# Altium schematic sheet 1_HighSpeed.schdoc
size 561 x 251 mm
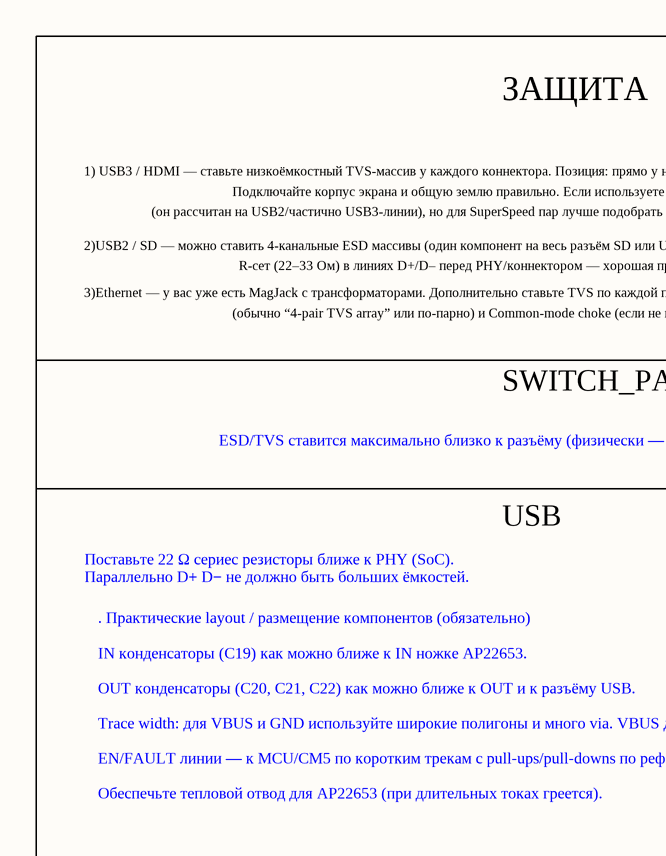
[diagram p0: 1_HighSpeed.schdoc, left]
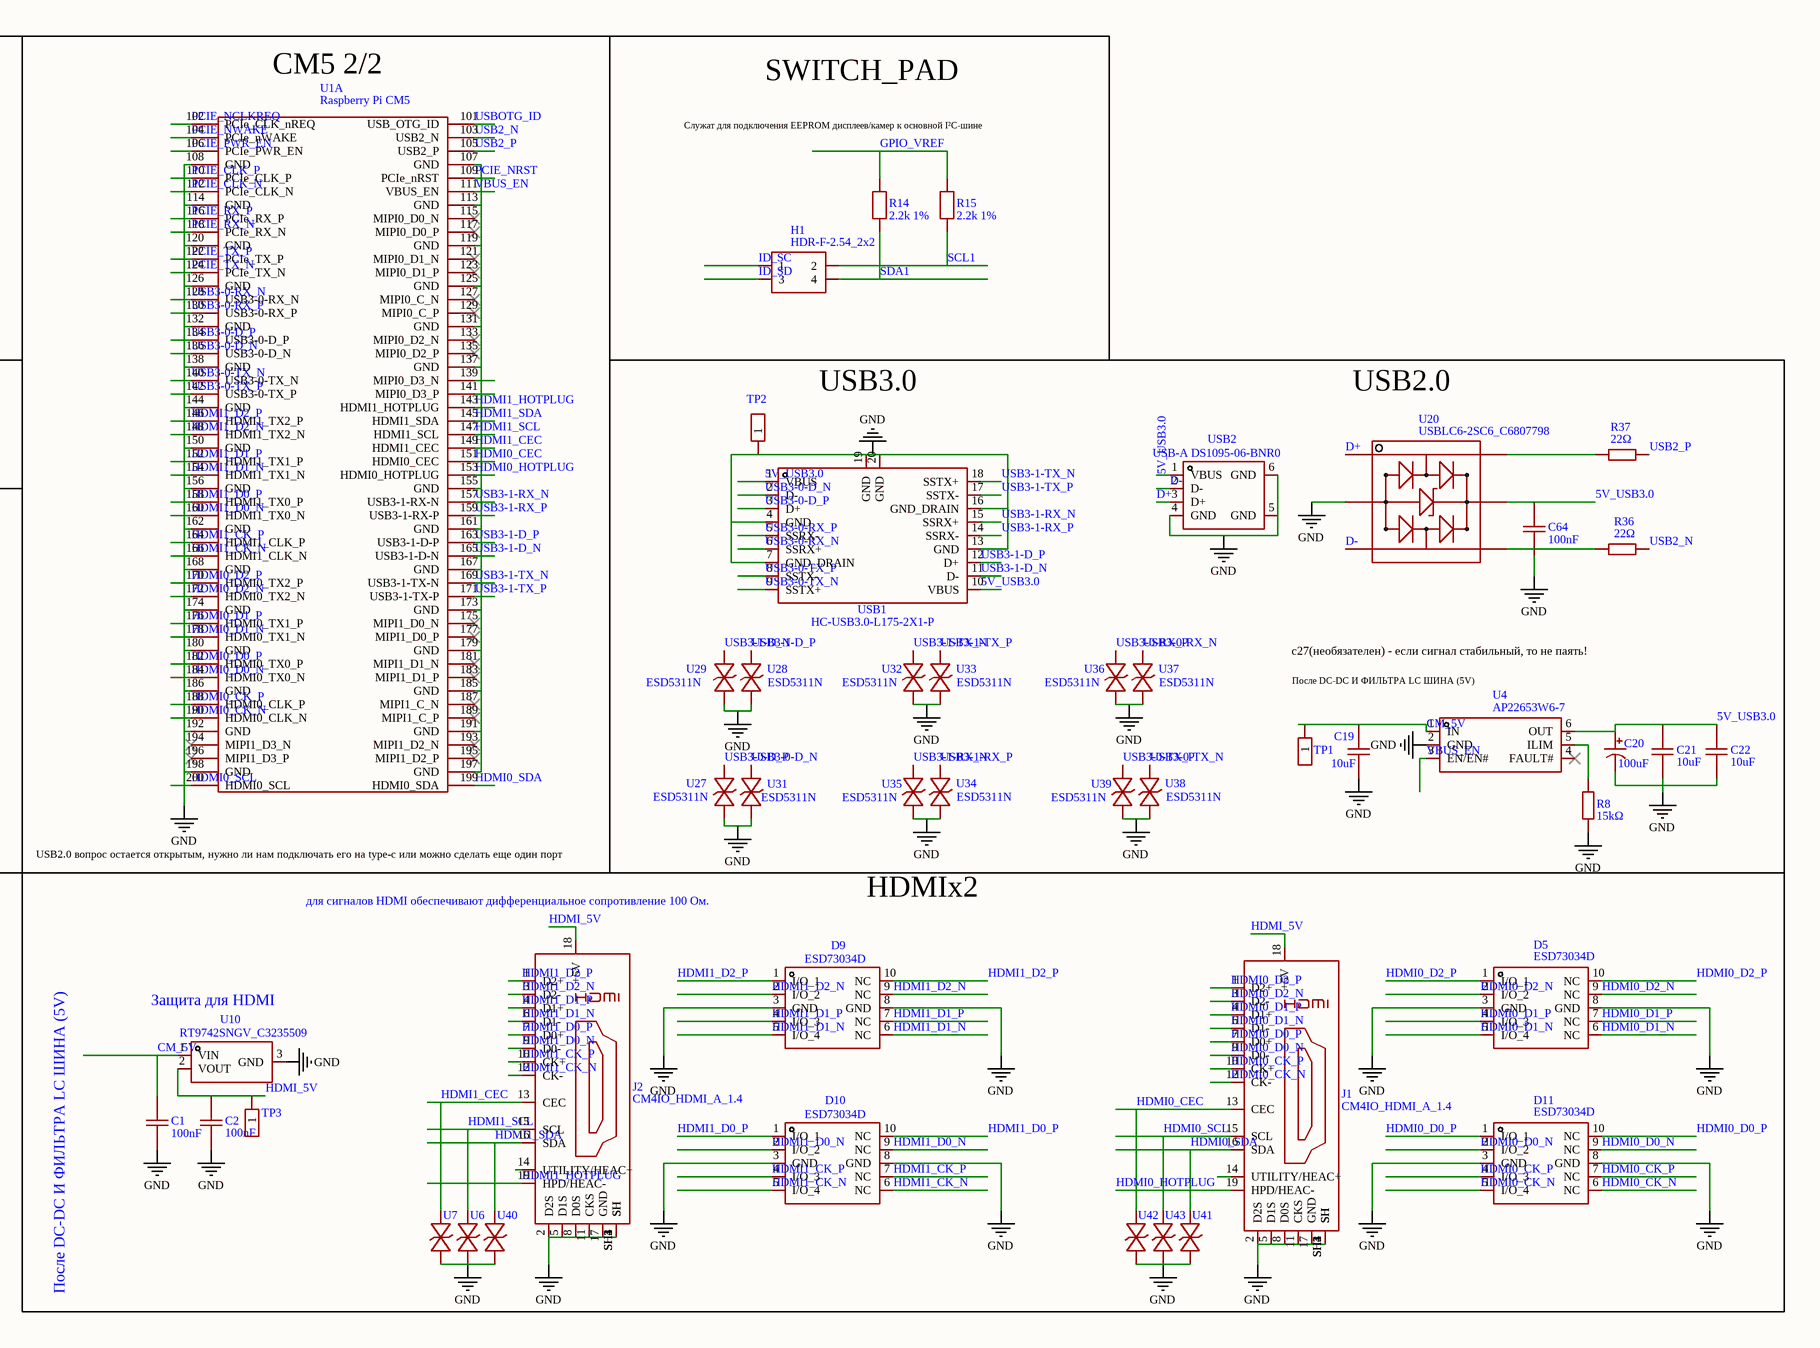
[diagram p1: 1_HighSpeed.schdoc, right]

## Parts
C1  100nF  [C0603]
C2  100nF  [C0603]
C19  10uF  [C0603]
C20  100uF  [CAP-SMD_BD6.3-L6.6-W6.6-LS7.6-FD]
C21  10uF  [C0603]
C22  10uF  [C0603]
C64  100nF  [C0402]
D5  ESD73034D  [DFN-10_L2.5-W1.0-P0.50-BL-2]
D9  ESD73034D  [DFN-10_L2.5-W1.0-P0.50-BL-2]
D10  ESD73034D  [DFN-10_L2.5-W1.0-P0.50-BL-2]
D11  ESD73034D  [DFN-10_L2.5-W1.0-P0.50-BL-2]
H1  HDR-F-2.54_2x2  [HDR-F-2.54_2X2]
J1  CM4IO_HDMI_A_1.4  [EDAC 690-019-298-412]
J2  CM4IO_HDMI_A_1.4  [EDAC 690-019-298-412]
R8  15kΩ  [R0603]
R14  2.2k 1%  [R0603]
R15  2.2k 1%  [R0603]
R36  22Ω  [R0402]
R37  22Ω  [R0402]
TP1  HDR-M-2.54_1x1  [HDR-M-2.54_1X1]  (value not drawn)
TP2  HDR-M-2.54_1x1  [HDR-M-2.54_1X1]  (value not drawn)
TP3  HDR-M-2.54_1x1  [HDR-M-2.54_1X1]  (value not drawn)
U1  Raspberry Pi CM5  [CM5IO:Raspberry-Pi-5-Compute-Module]  (part A of 2)
U4  AP22653W6-7  [SOT-23-6_L2.9-W1.6-P0.95-LS2.8-BR]
U6  ESD5311N  [DFN1006-2L-BI]  (value not drawn)
U7  ESD5311N  [DFN1006-2L-BI]  (value not drawn)
U10  RT9742SNGV_C3235509  [SOT-23-3_L2.9-W1.6-P1.90-LS2.8-BR]
U20  USBLC6-2SC6_C6807798  [SOT-23-6_L2.9-W1.6-P0.95-LS2.8-BL]
U27  ESD5311N  [DFN1006-2L-BI]
U28  ESD5311N  [DFN1006-2L-BI]
U29  ESD5311N  [DFN1006-2L-BI]
U31  ESD5311N  [DFN1006-2L-BI]
U32  ESD5311N  [DFN1006-2L-BI]
U33  ESD5311N  [DFN1006-2L-BI]
U34  ESD5311N  [DFN1006-2L-BI]
U35  ESD5311N  [DFN1006-2L-BI]
U36  ESD5311N  [DFN1006-2L-BI]
U37  ESD5311N  [DFN1006-2L-BI]
U38  ESD5311N  [DFN1006-2L-BI]
U39  ESD5311N  [DFN1006-2L-BI]
U40  ESD5311N  [DFN1006-2L-BI]  (value not drawn)
U41  ESD5311N  [DFN1006-2L-BI]  (value not drawn)
U42  ESD5311N  [DFN1006-2L-BI]  (value not drawn)
U43  ESD5311N  [DFN1006-2L-BI]  (value not drawn)
USB1  HC-USB3.0-L175-2X1-P  [USB-A-TH_H181-AF2R06-12ALCR]
USB2  USB-A DS1095-06-BNR0  [DS1095-06-BNR0]

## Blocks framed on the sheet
CM5 2/2: U1
SWITCH_PAD: H1 R14 R15
HDMIx2: C1 C2 D5 D9-D11 J1 J2 TP3 U6 U7 U10 U40-U43

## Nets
GND: C1.1 C2.1 C19.1 C20.2 C21.1 C22.1 C64.2 D5.3(GND) D5.8(GND) D9.3(GND) D9.8(GND) D10.3(GND) D10.8(GND) D11.3(GND) D11.8(GND) J1.2(D2S) J1.5(D1S) J1.8(D0S) J1.11(CKS) J1.17(GND) J1.SH1(SH) J1.SH2(SH) J1.SH3(SH) J1.SH4(SH) J2.2(D2S) J2.5(D1S) J2.8(D0S) J2.11(CKS) J2.17(GND) J2.SH1(SH) J2.SH2(SH) J2.SH3(SH) J2.SH4(SH) R8.1 TP2.1 U1.108(GND) U1.114(GND) U1.120(GND) U1.126(GND) U1.132(GND) U1.138(GND) U1.144(GND) U1.150(GND) U1.156(GND) U1.162(GND) U1.168(GND) U1.174(GND) U1.180(GND) U1.186(GND) U1.192(GND) U1.198(GND) U4.2(GND) U6.1 U7.1 U10.3(GND) U20.2(GND) U27.1 U28.1 U29.1 U31.1 U32.1 U33.1 U34.1 U35.1 U36.1 U37.1 U38.1 U39.1 U40.1 U41.1 U42.1 U43.1 USB1.4(GND) USB1.7(GND_DRAIN) USB1.13(GND) USB1.16(GND_DRAIN) USB1.19(GND) USB1.20(GND) USB2.4(GND) USB2.5(GND) USB2.6(GND)
5V_USB3.0: C20.1 C21.2 C22.2 C64.1 U4.6(OUT) U20.5(VCC) USB1.1(VBUS) USB1.10(VBUS) USB2.1(VBUS)
CM_5V: C1.2 C19.2 TP1.1 U4.1(IN) U10.1(VIN)
D+: U20.1(I/O1) USB2.3(D+)
D-: U20.3(I/O2) USB2.2(D-)
GPIO_VREF: R14.2 R15.2
HDMI0_CEC: J1.13(CEC) U1.151(HDMI0_CEC) U42.2
HDMI0_CK_N: D11.5(I/O_4) D11.6(NC) J1.12(CK-) U1.190(HDMI0_CLK_N)
HDMI0_CK_P: D11.4(I/O_3) D11.7(NC) J1.10(CK+) U1.188(HDMI0_CLK_P)
HDMI0_D0_N: D11.2(I/O_2) D11.9(NC) J1.9(D0-) U1.184(HDMI0_TX0_N)
HDMI0_D0_P: D11.1(I/O_1) D11.10(NC) J1.7(D0+) U1.182(HDMI0_TX0_P)
HDMI0_D1_N: D5.5(I/O_4) D5.6(NC) J1.6(D1-) U1.178(HDMI0_TX1_N)
HDMI0_D1_P: D5.4(I/O_3) D5.7(NC) J1.4(D1+) U1.176(HDMI0_TX1_P)
HDMI0_D2_N: D5.2(I/O_2) D5.9(NC) J1.3(D2-) U1.172(HDMI0_TX2_N)
HDMI0_D2_P: D5.1(I/O_1) D5.10(NC) J1.1(D2+) U1.170(HDMI0_TX2_P)
HDMI0_HOTPLUG: J1.19(HPD/HEAC-) U1.153(HDMI0_HOTPLUG)
HDMI0_SCL: J1.15(SCL) U1.200(HDMI0_SCL) U43.2
HDMI0_SDA: J1.16(SDA) U1.199(HDMI0_SDA) U41.2
HDMI1_CEC: J2.13(CEC) U1.149(HDMI1_CEC) U7.2
HDMI1_CK_N: D10.5(I/O_4) D10.6(NC) J2.12(CK-) U1.166(HDMI1_CLK_N)
HDMI1_CK_P: D10.4(I/O_3) D10.7(NC) J2.10(CK+) U1.164(HDMI1_CLK_P)
HDMI1_D0_N: D10.2(I/O_2) D10.9(NC) J2.9(D0-) U1.160(HDMI1_TX0_N)
HDMI1_D0_P: D10.1(I/O_1) D10.10(NC) J2.7(D0+) U1.158(HDMI1_TX0_P)
HDMI1_D1_N: D9.5(I/O_4) D9.6(NC) J2.6(D1-) U1.154(HDMI1_TX1_N)
HDMI1_D1_P: D9.4(I/O_3) D9.7(NC) J2.4(D1+) U1.152(HDMI1_TX1_P)
HDMI1_D2_N: D9.2(I/O_2) D9.9(NC) J2.3(D2-) U1.148(HDMI1_TX2_N)
HDMI1_D2_P: D9.1(I/O_1) D9.10(NC) J2.1(D2+) U1.146(HDMI1_TX2_P)
HDMI1_HOTPLUG: J2.19(HPD/HEAC-) U1.143(HDMI1_HOTPLUG)
HDMI1_SCL: J2.15(SCL) U1.147(HDMI1_SCL) U6.2
HDMI1_SDA: J2.16(SDA) U1.145(HDMI1_SDA) U40.2
HDMI_5V: C2.2 J1.18(+5V) J2.18(+5V) TP3.1 U10.2(VOUT)
ID_SC: H1.1
ID_SD: H1.3
PCIE_CLK_N: U1.112(PCIe_CLK_N)
PCIE_CLK_P: U1.110(PCIe_CLK_P)
PCIE_NCLKREQ: U1.102(PCIe_CLK_nREQ)
PCIE_NRST: U1.109(PCIe_nRST)
PCIE_NWAKE: U1.104(PCIe_nWAKE)
PCIE_PWR_EN: U1.106(PCIe_PWR_EN)
PCIE_RX_N: U1.118(PCIe_RX_N)
PCIE_RX_P: U1.116(PCIe_RX_P)
PCIE_TX_N: U1.124(PCIe_TX_N)
PCIE_TX_P: U1.122(PCIe_TX_P)
SCL1: H1.2 R15.1
SDA1: H1.4 R14.1
USB2_N: R36.1 U1.103(USB2_N)
USB2_P: R37.2 U1.105(USB2_P)
USB3-0-D_N: U1.136(USB3-0-D_N) U31.2 USB1.2(D-)
USB3-0-D_P: U1.134(USB3-0-D_P) U27.2 USB1.3(D+)
USB3-0-RX_N: U1.128(USB3-0-RX_N) U37.2 USB1.6(SSRX+)
USB3-0-RX_P: U1.130(USB3-0-RX_P) U36.2 USB1.5(SSRX-)
USB3-0-TX_N: U1.140(USB3-0-TX_N) U38.2 USB1.9(SSTX+)
USB3-0-TX_P: U1.142(USB3-0-TX_P) U39.2 USB1.8(SSTX-)
USB3-1-D_N: U1.165(USB3-1-D-N) U29.2 USB1.11(D-)
USB3-1-D_P: U1.163(USB3-1-D-P) U28.2 USB1.12(D+)
USB3-1-RX_N: U1.157(USB3-1-RX-N) U35.2 USB1.15(SSRX+)
USB3-1-RX_P: U1.159(USB3-1-RX-P) U34.2 USB1.14(SSRX-)
USB3-1-TX_N: U1.169(USB3-1-TX-N) U32.2 USB1.18(SSTX+)
USB3-1-TX_P: U1.171(USB3-1-TX-P) U33.2 USB1.17(SSTX-)
USBOTG_ID: U1.101(USB_OTG_ID)
VBUS_EN: U1.111(VBUS_EN) U4.3(EN/EN#)
NetR8_2: R8.2 U4.5(ILIM)
NetR36_2: R36.2 U20.4(I/O2)
NetR37_1: R37.1 U20.6(I/O1)
NetU1_107: U1.107(GND) U1.113(GND) U1.119(GND) U1.125(GND) U1.131(GND) U1.137(GND) U1.155(GND) U1.161(GND) U1.167(GND) U1.173(GND) U1.179(GND) U1.185(GND) U1.191(GND) U1.197(GND)

Not connected (* = marked no-connect by the designer): J1 14(UTILITY/HEAC+); J2 14(UTILITY/HEAC+); U1 115(MIPI0_D0_N)* 117(MIPI0_D0_P)* 121(MIPI0_D1_N)* 123(MIPI0_D1_P)* 127(MIPI0_C_N)* 129(MIPI0_C_P)* 133(MIPI0_D2_N)* 135(MIPI0_D2_P)* 139(MIPI0_D3_N) 141(MIPI0_D3_P) 175(MIPI1_D0_N)* 177(MIPI1_D0_P)* 181(MIPI1_D1_N)* 183(MIPI1_D1_P)* 187(MIPI1_C_N)* 189(MIPI1_C_P)* 193(MIPI1_D2_N)* 194(MIPI1_D3_N)* 195(MIPI1_D2_P)* 196(MIPI1_D3_P)*; U4 4(FAULT#)*

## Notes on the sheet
- ЗАЩИТА
- Служат для подключения EEPROM дисплеев/камер к основной I²C-шине
- 1) USB3 / HDMI — ставьте низкоёмкостный TVS-массив у каждого коннектора. Позиция: прямо у ножек разъёма (по максимуму ближе к штырям).
- (он рассчитан на USB2/частично USB3-линии), но для SuperSpeed пар лучше подобрать специально заявленный “USB3/HDMI” TVS.
- Подключайте корпус экрана и общую землю правильно. Если используете ESD5311N на USB — это нормальная практика
- 2)USB2 / SD — можно ставить 4-канальные ESD массивы (один компонент на весь разъём SD или USB2).
- R-сет (22–33 Ом) в линиях D+/D– перед PHY/коннектором — хорошая практика.
- 3)Ethernet — у вас уже есть MagJack с трансформаторами. Дополнительно ставьте TVS по каждой паре
- (обычно “4-pair TVS array” или по-парно) и Common-mode choke (если не интегрирован в разъём).
- SWITCH_PAD
- USB3.0
- USB2.0
- ESD/TVS ставится максимально близко к разъёму (физически — рядом с корпусом коннектора).
- Поставьте 22 Ω сериес резисторы ближе к PHY (SoC).
  Параллельно D+ D− не должно быть больших ёмкостей.
- USB
- . Практические layout / размещение компонентов (обязательно)
  IN конденсаторы (C19) как можно ближе к IN ножке AP22653.
  OUT конденсаторы (C20, C21, C22) как можно ближе к OUT и к разъёму USB.
  Trace width: для VBUS и GND используйте широкие полигоны и много via. VBUS должен выдерживать ток.
  EN/FAULT линии — к MCU/CM5 по коротким трекам с pull-ups/pull-downs по референсу.
  Обеспечьте тепловой отвод для AP22653 (при длительных токах греется).
- с27(необязателен) - если сигнал стабильный, то не паять!
- После DC-DC И ФИЛЬТРА LC ШИНА (5V)
- USB2.0 вопрос остается открытым, нужно ли нам подключать его на type-c или можно сделать еще один порт
- (near J2) для сигналов HDMI обеспечивают дифференциальное сопротивление 100 Ом.
- (near U10) Защита для HDMI

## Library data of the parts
C1 C2 = 100nF: Manufacturer: muRata(村田); Manufacturer Part: GRM188R72A104KA35D; Convert to PCB: yes; nameAlias: Value
C19 C21 C22 = 10uF: Manufacturer: muRata(村田); Manufacturer Part: GRM188R61C106KAALD; Convert to PCB: yes; nameAlias: Value; Contributor: LCSC
C20 = 100uF: Manufacturer: PANASONIC(松下); Manufacturer Part: EEEFK1E101XP; Convert to PCB: yes; nameAlias: Value
C64 = 100nF: Manufacturer: muRata(村田); Manufacturer Part: GCM155R71A104KA55D; Convert to PCB: yes; nameAlias: Value; Contributor: LCSC
D5 D9-D11 = ESD73034D: Manufacturer: TECH PUBLIC(台舟); Convert to PCB: yes; Contributor: lcsc
H1 = HDR-F-2.54_2x2: Convert to PCB: yes; Contributor: LCEDA_Lib
J1 J2 = CM4IO_HDMI_A_1.4: part description: HDMI Connector, Right Angle, 19 Contacts, Receptacle, Surface Mount, Surface Mount Right Angle; field4: Farnell; field5: 2614936; field6: 690-019-298-412; field7: EDAC; field8: UCON00802; sheetfile: CM4_HighSpeed.kicad_sch; sheetname: CM4_HighSpeed; Add into BOM: yes; Origin Footprint: CM4IO:EDAC 690-019-298-412; Contributor: Steve Forest
R8 = 15kΩ: Manufacturer: YAGEO(国巨); Manufacturer Part: RC0603FR-0715KL; Convert to PCB: yes; nameAlias: Value
R14 R15 = 2.2k 1%: Convert to PCB: yes; nameAlias: Value(Ω); Contributor: LCEDA_Lib
R36 R37 = 22Ω: Manufacturer: YAGEO(国巨); Manufacturer Part: RC0402FR-0722RL; Convert to PCB: yes; nameAlias: Value
TP1-TP3 = HDR-M-2.54_1x1: Convert to PCB: yes; Contributor: LCEDA_Lib
U1 = Raspberry Pi CM5: subpart_no: 1; Convert to PCB: yes; Origin Footprint: RASPBERRY_PI_CM5; Contributor: RobMel
U4 = AP22653W6-7: Manufacturer: DIODES(美台); Convert to PCB: yes; Contributor: LCSC
U6 U7 U27-U29 U31-U43 = ESD5311N: Manufacturer: TECH PUBLIC(台舟); Convert to PCB: yes; Contributor: lcsc
U10 = RT9742SNGV_C3235509: Manufacturer: RICHTEK(立锜); Convert to PCB: yes; Contributor: lcsc
U20 = USBLC6-2SC6_C6807798: Manufacturer: FUXINSEMI(富芯森美); Convert to PCB: yes; Contributor: lcsc
USB1 = HC-USB3.0-L175-2X1-P: Manufacturer: HC(虹成电子); Convert to PCB: yes; Contributor: lcsc
USB2 = USB-A DS1095-06-BNR0: Manufacturer: Zhendin; Manufacturer Part: DS1095-06BNR0; Convert to PCB: yes; Origin Footprint: USB-A DS1095-06-BNR); Contributor: Рустем Равилов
